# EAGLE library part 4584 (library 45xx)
Hex SCHMITT TRIGGER (74C14)
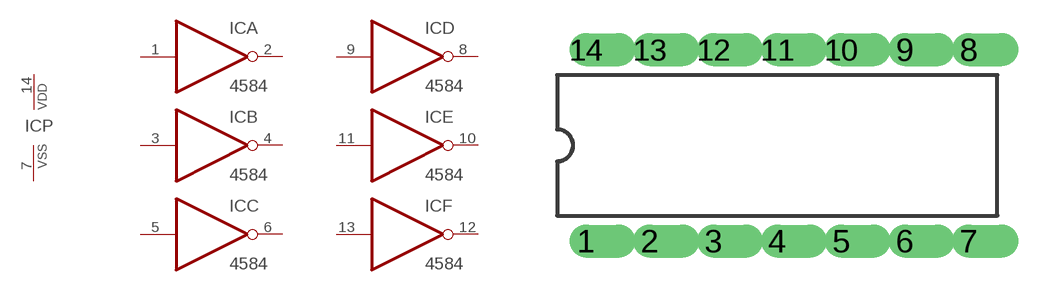
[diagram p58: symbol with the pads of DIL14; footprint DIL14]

Designator prefix IC; gates A=4584 B=4584 C=4584 D=4584 E=4584 F=4584 P=PWRN

## 4584N  [DIL14]
1  A:I  in
2  A:O  out
3  B:I  in
4  B:O  out
5  C:I  in
6  C:O  out
7  P:VSS  pwr
8  D:O  out
9  D:I  in
10  E:O  out
11  E:I  in
12  F:O  out
13  F:I  in
14  P:VDD  pwr

## Footprint DIL14 (pad centres in mm)
Dual In Line
drill 0.813 offset: 1 -7.62,-3.81; 2 -5.08,-3.81; 3 -2.54,-3.81; 4 0,-3.81; 5 2.54,-3.81; 6 5.08,-3.81; 7 7.62,-3.81; 8 7.62,3.81; 9 5.08,3.81; 10 2.54,3.81; 11 0,3.81; 12 -2.54,3.81; 13 -5.08,3.81; 14 -7.62,3.81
